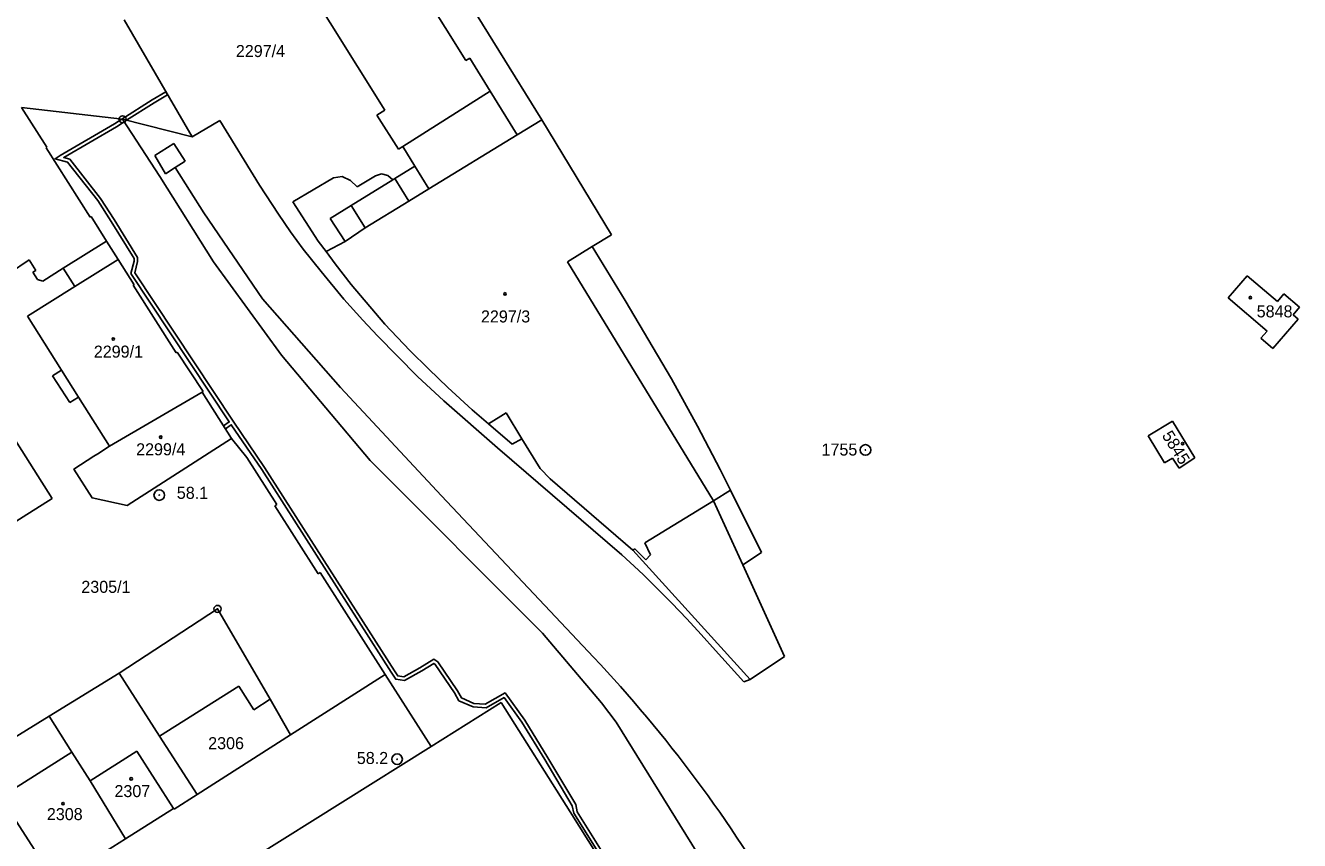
# Model space of a CAD drawing. Extents: x -735092 to -733385, y -1122435 to -1118992.
# Drawn here: x -734684.8 to -734504.8, y -1119855 to -1119739.8 of the extents above; entities that cross this region are included whole.
import ezdxf

# ---------------------------------------------------------------- set-up
doc = ezdxf.new("R2010")
doc.units = 0
for name, color, linetype in [('Vrstva 1', 7, 'Continuous'), ('Vrstva 10', 7, 'Continuous'), ('Vrstva 17', 7, 'Continuous'), ('Vrstva 18', 7, 'Continuous'), ('Vrstva 19', 7, 'Continuous'), ('Vrstva 25', 7, 'Continuous'), ('Vrstva 27', 7, 'Continuous'), ('Vrstva 4', 7, 'Continuous')]:
    doc.layers.add(name, color=color, linetype=linetype)

msp = doc.modelspace()

# ---------------------------------------------------------------- linework, layer by layer
at = {"layer": 'Vrstva 1'}
for points in [[(-734660.48, -1119674.74), (-734611.9, -1119753.15)], [(-734645.65, -1119733.23), (-734634.05, -1119751.76)], [(-734670.91, -1119738.99), (-734661.3, -1119755.55)], [(-734631.54, -1119756.89), (-734619.16, -1119749.09)], [(-734619.16, -1119749.09), (-734615.35, -1119755.24)], [(-734685.38, -1119751.4), (-734681.79, -1119757)], [(-734685.38, -1119751.4), (-734671.12, -1119753.05)], [(-734635.18, -1119752.48), (-734634.05, -1119751.76)], [(-734671.12, -1119753.05), (-734665.85, -1119761.13)], [(-734671.12, -1119753.05), (-734661.3, -1119755.55)], [(-734661.3, -1119755.55), (-734657.38, -1119753.24)], [(-734657.38, -1119753.24), (-734651.75, -1119762.36)], [(-734635.18, -1119752.48), (-734632.14, -1119757.27)], [(-734615.35, -1119755.24), (-734611.9, -1119753.15)], [(-734611.9, -1119753.15), (-734602.02, -1119769.37)], [(-734681.91, -1119757.08), (-734681.79, -1119757)], [(-734681.91, -1119757.08), (-734675.7, -1119766.89)], [(-734632.14, -1119757.27), (-734631.54, -1119756.89)], [(-734631.54, -1119756.89), (-734629.81, -1119759.69)], [(-734635.4, -1119761.06), (-734634.53, -1119760.76)], [(-734634.53, -1119760.76), (-734633.62, -1119760.99)], [(-734632.65, -1119761.43), (-734629.81, -1119759.69)], [(-734665.85, -1119761.13), (-734658.29, -1119773.18)], [(-734651.75, -1119762.36), (-734649.09, -1119766.46)], [(-734647.05, -1119764.73), (-734641.33, -1119761.34)], [(-734641.33, -1119761.34), (-734640.07, -1119761.15)], [(-734640.07, -1119761.15), (-734638.89, -1119761.69)], [(-734638.89, -1119761.69), (-734637.99, -1119762.58)], [(-734637.99, -1119762.58), (-734635.4, -1119761.06)], [(-734633.62, -1119760.99), (-734632.95, -1119761.59)], [(-734632.95, -1119761.59), (-734632.65, -1119761.43)], [(-734647.05, -1119764.73), (-734643.5, -1119770.27)], [(-734675.7, -1119766.89), (-734675.57, -1119766.81)], [(-734675.57, -1119766.81), (-734673.37, -1119770.28)], [(-734649.09, -1119766.46), (-734647.37, -1119768.96)], [(-734647.37, -1119768.96), (-734645.59, -1119771.41)], [(-734604.75, -1119771.04), (-734602.02, -1119769.37)], [(-734679.51, -1119774.11), (-734673.37, -1119770.28)], [(-734673.37, -1119770.28), (-734671.75, -1119772.85)], [(-734645.59, -1119771.41), (-734643.08, -1119774.58)], [(-734643.5, -1119770.27), (-734642.37, -1119771.72)], [(-734642.37, -1119771.72), (-734641.1, -1119773.48)], [(-734604.75, -1119771.04), (-734600.11, -1119778.66)], [(-734687.08, -1119774.77), (-734684.29, -1119772.89)], [(-734684.29, -1119772.89), (-734683.35, -1119774.41)], [(-734671.75, -1119772.85), (-734669.48, -1119776.42)], [(-734658.29, -1119773.18), (-734648.67, -1119786.38)], [(-734641.1, -1119773.48), (-734638.83, -1119776.39)], [(-734683.77, -1119774.67), (-734683.35, -1119774.41)], [(-734683.77, -1119774.67), (-734683.12, -1119775.7)], [(-734682.4, -1119775.92), (-734679.51, -1119774.11)], [(-734679.51, -1119774.11), (-734677.88, -1119776.69)], [(-734643.08, -1119774.58), (-734639.85, -1119778.45)], [(-734514.93, -1119778.29), (-734512.22, -1119775.16)], [(-734512.22, -1119775.16), (-734507.97, -1119778.8)], [(-734684.56, -1119780.87), (-734677.88, -1119776.69)], [(-734683.12, -1119775.7), (-734682.4, -1119775.92)], [(-734669.61, -1119776.5), (-734669.48, -1119776.42)], [(-734669.61, -1119776.5), (-734663.52, -1119786.04)], [(-734638.83, -1119776.39), (-734634.08, -1119781.98)], [(-734698.92, -1119778.46), (-734681.04, -1119806.62)], [(-734639.85, -1119778.45), (-734637.17, -1119781.44)], [(-734600.11, -1119778.66), (-734593.54, -1119789.7)], [(-734514.93, -1119778.29), (-734509.43, -1119782.99)], [(-734507.97, -1119778.8), (-734507.05, -1119777.72)], [(-734507.05, -1119777.72), (-734504.84, -1119779.62)], [(-734505.76, -1119780.69), (-734504.84, -1119779.62)], [(-734505.76, -1119780.69), (-734505.05, -1119781.3)], [(-734684.56, -1119780.87), (-734679.75, -1119788.48)], [(-734637.17, -1119781.44), (-734635.1, -1119783.66)], [(-734634.08, -1119781.98), (-734630.52, -1119785.71)], [(-734508.6, -1119785.45), (-734505.05, -1119781.3)], [(-734635.1, -1119783.66), (-734629.44, -1119789.4)], [(-734510.32, -1119783.96), (-734509.43, -1119782.99)], [(-734510.32, -1119783.96), (-734508.6, -1119785.45)], [(-734663.52, -1119786.04), (-734663.38, -1119785.95)], [(-734663.38, -1119785.95), (-734659.74, -1119791.5)], [(-734630.52, -1119785.71), (-734627.86, -1119788.35)], [(-734648.67, -1119786.38), (-734636.15, -1119801.26)], [(-734681, -1119789.31), (-734679.75, -1119788.48)], [(-734681, -1119789.31), (-734678.55, -1119793.06)], [(-734629.44, -1119789.4), (-734625.73, -1119792.81)], [(-734627.86, -1119788.35), (-734625.14, -1119790.95)], [(-734593.54, -1119789.7), (-734589.91, -1119796.41)], [(-734659.87, -1119791.59), (-734659.74, -1119791.5)], [(-734625.14, -1119790.95), (-734621.74, -1119794.1)], [(-734678.55, -1119793.06), (-734677.33, -1119792.3)], [(-734677.33, -1119792.3), (-734672.94, -1119799.25)], [(-734672.94, -1119799.25), (-734659.87, -1119791.59)], [(-734659.87, -1119791.59), (-734655.73, -1119798.13)], [(-734625.73, -1119792.81), (-734618.13, -1119799.45)], [(-734621.74, -1119794.1), (-734619.43, -1119796.07)], [(-734619.43, -1119796.07), (-734616.09, -1119798.97)], [(-734589.91, -1119796.41), (-734586.7, -1119802.54)], [(-734526.21, -1119797.77), (-734522.77, -1119795.7)], [(-734522.77, -1119795.7), (-734519.62, -1119800.89)], [(-734670.45, -1119807.61), (-734655.73, -1119798.13)], [(-734655.73, -1119798.13), (-734653.58, -1119800.84)], [(-734616.09, -1119798.97), (-734614.73, -1119798.18)], [(-734614.73, -1119798.18), (-734612.1, -1119802.41)], [(-734526.21, -1119797.77), (-734523.91, -1119801.59)], [(-734675.15, -1119800.65), (-734674.61, -1119800.31)], [(-734674.61, -1119800.31), (-734672.94, -1119799.25)], [(-734618.13, -1119799.45), (-734600.56, -1119814.57)], [(-734675.15, -1119800.65), (-734677.98, -1119802.47), (-734675.42, -1119806.55), (-734670.45, -1119807.61)], [(-734653.58, -1119800.84), (-734649.34, -1119807.48)], [(-734636.15, -1119801.26), (-734611.78, -1119825.65)], [(-734523.91, -1119801.59), (-734522.77, -1119800.92)], [(-734522.77, -1119800.92), (-734521.86, -1119802.34)], [(-734521.86, -1119802.34), (-734519.62, -1119800.89)], [(-734612.1, -1119802.41), (-734610.72, -1119803.83)], [(-734610.72, -1119803.83), (-734599.03, -1119813.91)], [(-734586.7, -1119802.54), (-734585.24, -1119805.43)], [(-734585.24, -1119805.43), (-734580.86, -1119814.28)], [(-734689.28, -1119811.79), (-734681.04, -1119806.62)], [(-734649.61, -1119807.65), (-734649.34, -1119807.48)], [(-734649.61, -1119807.65), (-734643.47, -1119817.26)], [(-734600.56, -1119814.57), (-734598.24, -1119816.76)], [(-734599.03, -1119813.91), (-734582.44, -1119832.18)], [(-734583.49, -1119816), (-734580.86, -1119814.28)], [(-734598.24, -1119816.76), (-734597.47, -1119817.48)], [(-734583.49, -1119816), (-734577.6, -1119828.96)], [(-734643.47, -1119817.26), (-734643.2, -1119817.09)], [(-734643.2, -1119817.09), (-734634.01, -1119831.48)], [(-734597.47, -1119817.48), (-734595.63, -1119819.3)], [(-734595.63, -1119819.3), (-734593.5, -1119821.43)], [(-734593.5, -1119821.43), (-734591.39, -1119823.62)], [(-734671.6, -1119831.3), (-734657.7, -1119822.23)], [(-734657.7, -1119822.23), (-734650.28, -1119835)], [(-734591.39, -1119823.62), (-734589.37, -1119825.85)], [(-734611.78, -1119825.65), (-734603.43, -1119835.5)], [(-734589.37, -1119825.85), (-734587.35, -1119828.11)], [(-734587.35, -1119828.11), (-734583.34, -1119832.53)], [(-734582.44, -1119832.18), (-734577.6, -1119828.96)], [(-734681.48, -1119837.39), (-734671.6, -1119831.3)], [(-734671.6, -1119831.3), (-734665.89, -1119840.19)], [(-734647.37, -1119840.02), (-734634.01, -1119831.48)], [(-734634.01, -1119831.48), (-734627.51, -1119841.65)], [(-734583.34, -1119832.53), (-734582.44, -1119832.18)], [(-734650.28, -1119835), (-734647.37, -1119840.02)], [(-734627.51, -1119841.65), (-734617.61, -1119835.45)], [(-734617.61, -1119835.45), (-734607.9, -1119850.91)], [(-734603.43, -1119835.5), (-734601.4, -1119838.24)], [(-734686.28, -1119840.35), (-734681.48, -1119837.39)], [(-734681.48, -1119837.39), (-734678.28, -1119842.45)], [(-734601.4, -1119838.24), (-734520.59, -1119968.54)], [(-734660.59, -1119848.47), (-734647.37, -1119840.02)], [(-734665.89, -1119840.19), (-734660.59, -1119848.47)], [(-734652.49, -1119857.29), (-734627.51, -1119841.65)], [(-734678.28, -1119842.45), (-734675.7, -1119846.53)], [(-734675.7, -1119846.53), (-734670.69, -1119854.73)], [(-734663.82, -1119850.53), (-734660.59, -1119848.47)], [(-734687.82, -1119849.58), (-734680.55, -1119860.93)], [(-734670.69, -1119854.73), (-734663.9, -1119850.41)], [(-734663.9, -1119850.41), (-734663.82, -1119850.53)], [(-734607.9, -1119850.91), (-734584.98, -1119887.37)], [(-734680.55, -1119860.93), (-734670.69, -1119854.73)]]:
    msp.add_lwpolyline(points, dxfattribs=at)
at = {"layer": 'Vrstva 10'}
for points in [[(-734663.67, -1119759.87), (-734659.62, -1119766.27)], [(-734659.62, -1119766.27), (-734651.35, -1119778.44)], [(-734651.35, -1119778.44), (-734640.32, -1119790.95)], [(-734640.32, -1119790.95), (-734626.05, -1119806.23)], [(-734626.05, -1119806.23), (-734604.56, -1119829.03)]]:
    msp.add_lwpolyline(points, dxfattribs=at)
msp.add_arc((-734750.581, -1119965.773), 200.052, 30.16423, 43.12104, dxfattribs=at)
at = {"layer": 'Vrstva 25'}
for centre, radius in [((-734671.12, -1119753.05), 0.5), ((-734671.12, -1119753.05), 0.032), ((-734617.08, -1119777.72), 0.175), ((-734511.79, -1119778.24), 0.175), ((-734672.43, -1119784.1), 0.175), ((-734665.72, -1119797.96), 0.175), ((-734521.35, -1119798.88), 0.175), ((-734566.16, -1119799.77), 0.75), ((-734566.16, -1119799.77), 0.032), ((-734665.93, -1119806.15), 0.75), ((-734665.93, -1119806.15), 0.032), ((-734657.7, -1119822.23), 0.5), ((-734657.7, -1119822.23), 0.032), ((-734632.33, -1119843.46), 0.75), ((-734632.33, -1119843.46), 0.032), ((-734669.9, -1119846.24), 0.175), ((-734679.52, -1119849.75), 0.175)]:
    msp.add_circle(centre, radius, dxfattribs=at)
at = {"layer": 'Vrstva 27'}
for points in [[(-734669.94, -1119774.83), (-734669.49, -1119773.09), (-734669.49, -1119772.73), (-734672.73, -1119767.48), (-734674.62, -1119764.52), (-734678.88, -1119759.12), (-734680.65, -1119758.63), (-734679.92, -1119758.17), (-734672.24, -1119753.69), (-734671.21, -1119753.04), (-734666.91, -1119750.32), (-734665, -1119749.17)], [(-734664.76, -1119749.59), (-734666.65, -1119750.74), (-734670.54, -1119753.2), (-734671.12, -1119753.05), (-734670.88, -1119753.42), (-734671.98, -1119754.11), (-734679.42, -1119758.45), (-734678.58, -1119758.68), (-734674.22, -1119764.24), (-734672.31, -1119767.22), (-734668.99, -1119772.59), (-734668.99, -1119773.15), (-734669.4, -1119774.74), (-734655.49, -1119795.72), (-734651.04, -1119802.23), (-734632.7, -1119830.99), (-734632.23, -1119831.7), (-734631.38, -1119831.84), (-734629.11, -1119830.54), (-734627.14, -1119829.34), (-734626.58, -1119829.71), (-734623.8, -1119833.81), (-734623.23, -1119834.8), (-734621.48, -1119835.58), (-734619.88, -1119835.69), (-734617.07, -1119834.1), (-734614.3, -1119837.95), (-734611.03, -1119843.25), (-734607.1, -1119849.86), (-734606.9, -1119850.89), (-734596.75, -1119867.09)], [(-734665, -1119749.17), (-734664.76, -1119749.59)], [(-734656.84, -1119796.37), (-734656.04, -1119795.8), (-734669.94, -1119774.83)], [(-734656.58, -1119796.79), (-734656.84, -1119796.37)], [(-734597.17, -1119867.35), (-734607.38, -1119851.07), (-734607.58, -1119850.04), (-734611.45, -1119843.51), (-734614.72, -1119838.23), (-734617.21, -1119834.76), (-734619.76, -1119836.19), (-734621.6, -1119836.08), (-734623.59, -1119835.2), (-734624.22, -1119834.07), (-734626.94, -1119830.07), (-734627.15, -1119829.94), (-734628.83, -1119830.96), (-734631.28, -1119832.36), (-734632.53, -1119832.16), (-734633.19, -1119831.15), (-734651.46, -1119802.51), (-734655.76, -1119796.21), (-734656.58, -1119796.79)]]:
    msp.add_lwpolyline(points, dxfattribs=at)
at = {"layer": 'Vrstva 4'}
for points in [[(-734634.29, -1119726.03), (-734622.62, -1119744.76)], [(-734622.62, -1119744.76), (-734622.06, -1119744.41)], [(-734622.06, -1119744.41), (-734619.16, -1119749.09)], [(-734627.86, -1119762.86), (-734615.35, -1119755.24)], [(-734666.57, -1119758.16), (-734663.88, -1119756.48)], [(-734663.88, -1119756.48), (-734662.29, -1119758.98)], [(-734666.57, -1119758.16), (-734665.05, -1119760.75)], [(-734663.67, -1119759.87), (-734662.29, -1119758.98)], [(-734665.05, -1119760.75), (-734663.67, -1119759.87)], [(-734629.81, -1119759.69), (-734627.86, -1119762.86)], [(-734638.81, -1119765.23), (-734632.95, -1119761.59)], [(-734632.65, -1119761.43), (-734630.69, -1119764.61)], [(-734630.69, -1119764.61), (-734627.86, -1119762.86)], [(-734641.78, -1119767.07), (-734638.81, -1119765.23)], [(-734638.81, -1119765.23), (-734636.85, -1119768.41)], [(-734636.85, -1119768.41), (-734630.69, -1119764.61)], [(-734641.78, -1119767.07), (-734639.68, -1119770.3)], [(-734639.68, -1119770.3), (-734636.85, -1119768.41)], [(-734642.37, -1119771.72), (-734639.68, -1119770.3)], [(-734608.27, -1119773.18), (-734604.75, -1119771.04)], [(-734677.88, -1119776.69), (-734671.75, -1119772.85)], [(-734608.27, -1119773.18), (-734587.61, -1119806.97)], [(-734679.75, -1119788.48), (-734677.33, -1119792.3)], [(-734619.43, -1119796.07), (-734616.9, -1119794.53)], [(-734616.9, -1119794.53), (-734614.73, -1119798.18)], [(-734587.61, -1119806.97), (-734585.24, -1119805.43)], [(-734597.32, -1119812.88), (-734587.61, -1119806.97)], [(-734587.61, -1119806.97), (-734583.49, -1119816)], [(-734597.32, -1119812.88), (-734596.52, -1119814.58)], [(-734599.03, -1119813.91), (-734598.73, -1119813.73)], [(-734598.73, -1119813.73), (-734597.21, -1119815.3)], [(-734597.21, -1119815.3), (-734596.52, -1119814.58)], [(-734665.89, -1119840.19), (-734654.7, -1119833.14)], [(-734654.7, -1119833.14), (-734652.58, -1119836.5)], [(-734652.58, -1119836.5), (-734650.28, -1119835)], [(-734688.31, -1119848.82), (-734678.28, -1119842.45)], [(-734675.7, -1119846.53), (-734669.1, -1119842.32)], [(-734669.1, -1119842.32), (-734663.9, -1119850.41)]]:
    msp.add_lwpolyline(points, dxfattribs=at)

# ---------------------------------------------------------------- texts
at = {"layer": 'Vrstva 17'}
for s, p in [('1755', (-734572.37, -1119800.56)), ('58.1', (-734663.45, -1119806.68)), ('58.2', (-734638.02, -1119844.14))]:
    msp.add_text(s, height=1.7, dxfattribs=at).set_placement(p)
at = {"layer": 'Vrstva 18'}
for s, p in [('2297/4', (-734655.11, -1119744.26)), ('2306', (-734659.02, -1119842.05))]:
    msp.add_text(s, height=1.7, dxfattribs=at).set_placement(p)
at = {"layer": 'Vrstva 19'}
for s, p in [('2297/3', (-734620.48, -1119781.76)), ('5848', (-734510.89, -1119781.04)), ('2299/1', (-734675.178, -1119786.73)), ('2299/4', (-734669.198, -1119800.53)), ('2305/1', (-734676.94, -1119819.96)), ('2307', (-734672.26, -1119848.82)), ('2308', (-734681.81, -1119852.07))]:
    msp.add_text(s, height=1.7, dxfattribs=at).set_placement(p)
msp.add_text('5845', height=1.7, rotation=302.1024, dxfattribs=at).set_placement((-734524.345, -1119797.723))

doc.saveas('drawing.dxf')
